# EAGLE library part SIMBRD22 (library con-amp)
AMP connector
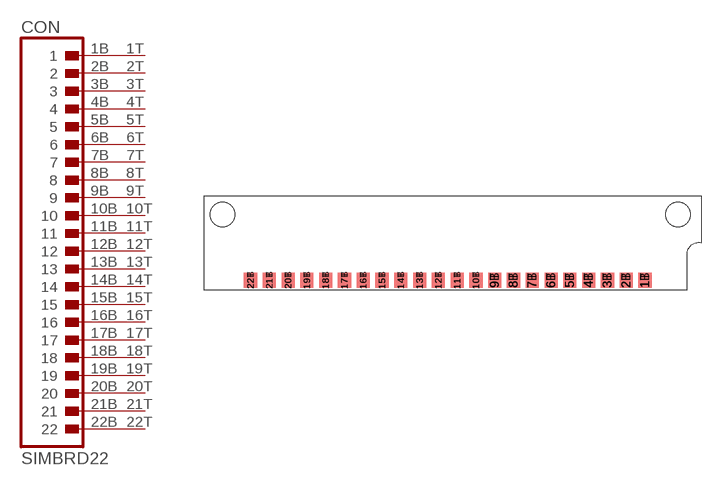
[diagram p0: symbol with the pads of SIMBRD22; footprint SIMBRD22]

Designator prefix CON

## SIMBRD22 (OC_FARNELL: unknown; OC_NEWARK: unknown)  [SIMBRD22]
1B  1  pas
1T  A1  pas
2B  2  pas
2T  A2  pas
3B  3  pas
3T  A3  pas
4B  4  pas
4T  A4  pas
5B  5  pas
5T  A5  pas
6B  6  pas
6T  A6  pas
7B  7  pas
7T  A7  pas
8B  8  pas
8T  A8  pas
9B  9  pas
9T  A9  pas
10B  10  pas
10T  A10  pas
11B  11  pas
11T  A11  pas
12B  12  pas
12T  A12  pas
13B  13  pas
13T  A13  pas
14B  14  pas
14T  A14  pas
15B  15  pas
15T  A15  pas
16B  16  pas
16T  A16  pas
17B  17  pas
17T  A17  pas
18B  18  pas
18T  A18  pas
19B  19  pas
19T  A19  pas
20B  20  pas
20T  A20  pas
21B  21  pas
21T  A21  pas
22B  22  pas
22T  A22  pas

## Footprint SIMBRD22 (pad centres in mm)
SIMM Modul
smd 1.778 x 2.032 bottom: 1B 26.67,-6.35; 2B 24.13,-6.35; 3B 21.59,-6.35; 4B 19.05,-6.35; 5B 16.51,-6.35; 6B 13.97,-6.35; 7B 11.43,-6.35; 8B 8.89,-6.35; 9B 6.35,-6.35; 10B 3.81,-6.35; 11B 1.27,-6.35; 12B -1.27,-6.35; 13B -3.81,-6.35; 14B -6.35,-6.35; 15B -8.89,-6.35; 16B -11.43,-6.35; 17B -13.97,-6.35; 18B -16.51,-6.35; 19B -19.05,-6.35; 20B -21.59,-6.35; 21B -24.13,-6.35; 22B -26.67,-6.35
smd 1.778 x 2.032: 1T 26.67,-6.35; 2T 24.13,-6.35; 3T 21.59,-6.35; 4T 19.05,-6.35; 5T 16.51,-6.35; 6T 13.97,-6.35; 7T 11.43,-6.35; 8T 8.89,-6.35; 9T 6.35,-6.35; 10T 3.81,-6.35; 11T 1.27,-6.35; 12T -1.27,-6.35; 13T -3.81,-6.35; 14T -6.35,-6.35; 15T -8.89,-6.35; 16T -11.43,-6.35; 17T -13.97,-6.35; 18T -16.51,-6.35; 19T -19.05,-6.35; 20T -21.59,-6.35; 21T -24.13,-6.35; 22T -26.67,-6.35
hole 3.302 at -30.48,2.54
hole 3.302 at 31.115,2.54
